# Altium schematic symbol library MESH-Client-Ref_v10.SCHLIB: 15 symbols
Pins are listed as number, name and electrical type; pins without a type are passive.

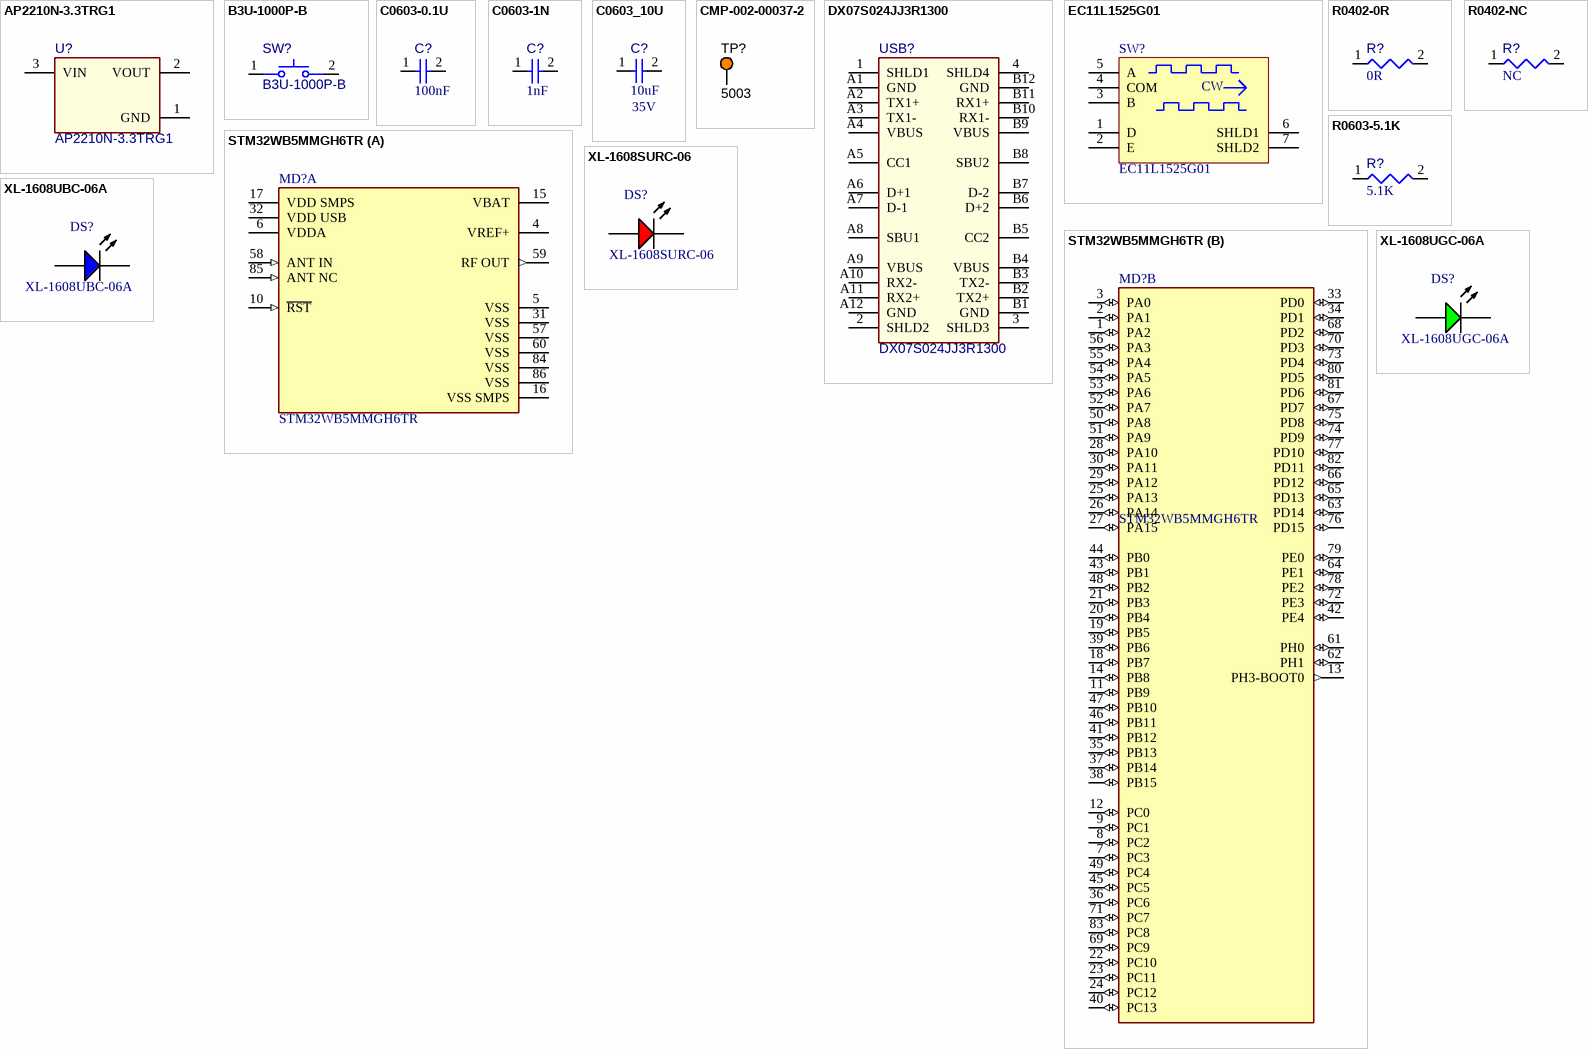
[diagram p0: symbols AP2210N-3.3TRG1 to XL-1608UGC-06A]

## AP2210N-3.3TRG1
designator U?
IC REG LINEAR 3.3V 300MA SOT23-3; Manufacturer: Diodes Incorporated
footprint SOT23-3 (SOT23, 3-Leads, Body 2.96x2.83mm, Pitch 0.95mm, IPC Medium Density)
pins: 1 GND (power) "Common ground", 2 VOUT (power) "Output voltage. A 1-uF Low ESR capacitor should be connected to this pin. Connect this output to the load circuit. An internal 280 Ohm discharge resistor prevents a charge remaining on VOUT when VEN is low.", 3 VIN (power) "Input voltage supply. A 1-µF capacitor should be connected at this input."

## B3U-1000P-B
designator SW?
Ultra-small Surface-mounting Tactile Switches with High Contact Reliability, SPST-NO, -25 to 70 degC, 2-Pin SMD, RoHS, Tape and Reel; Manufacturer: Omron; Voltage Rating: 12V
footprint OMRON-B3U-1000P-2-B_V (SMT, 2-Leads, Body 3x2.5mm)
pins: 1, 2

## C0603-0.1U
designator C?, comment value 100nF  (hidden comment: 0.1uF)
CAP CER 0.1UF 16V X7R 0603; Manufacturer: Murata Electronics; Part Number: GCJ188R71C104KA01D
footprint C0603 (Chip Capacitor, 2-Leads, Body 1.60x0.80mm, IPC Medium Density)
pins: 1, 2

## C0603-1N
designator C?, comment 1nF
CAP CER 1000PF 50V C0G/NP0 0603; Manufacturer: Murata Electronics; Part Number: GRM1885C1H102JA01D
footprint C0603 (Chip Capacitor, 2-Leads, Body 1.60x0.80mm, IPC Medium Density)
pins: 1, 2

## C0603_10U
designator C?, comment Voltage Rating: 35V  (hidden comment: 10uF)
CAP CER 10UF 35V X5R 0603; Part Number: GRM188R6YA106MA73D; Manufacturer: Murata
footprint C0603 (Chip Capacitor, 2-Leads, Body 1.60x0.80mm, IPC Medium Density)
pins: 1, 2

## CMP-002-00037-2
designator TP?, comment 5003  (no BOM)
Test Point, Orange, Height 4.6 mm, Tail Length 3 mm, 1-Pin THD, RoHS; Manufacturer: Keystone; Manufacturer 1: Keystone Electronics
footprint KSTN-5003 (Test Point, Through Hole, Dia 2.54mm)
pins: 1

## DX07S024JJ3R1300
designator USB?
USB-C Connector, 20 V, 1.25 A, -30 to 80 degC, RoHS, Tape and Reel; Manufacturer: JAE Electronics; Gender: Receptacle
footprint JAE-DX07S024JJ3_V (THD, 24-Leads, Body 8.17x8.94mm, Pitch 0.5mm)
pins: 1 SHLD1, 2 SHLD2, 3 SHLD3, 4 SHLD4, A1 GND, A2 TX1+, A3 TX1-, A4 VBUS, A5 CC1, A6 D+1, A7 D-1, A8 SBU1, A9 VBUS, A10 RX2-, A11 RX2+, A12 GND, B1 GND, B2 TX2+, B3 TX2-, B4 VBUS, B5 CC2, B6 D+2, B7 D-2, B8 SBU2, B9 VBUS, B10 RX1-, B11 RX1+, B12 GND

## EC11L1525G01
designator SW?
Plugin Rotary Encoders ROHS; Manufacturer: ALPSALPINE
footprint EC11L1525G01
pins: 1 D, 2 E, 3 B "Channel B", 4 COM "Common", 5 A "Channel A", 6 SHLD1, 7 SHLD2

## R0402-0R
designator R?, comment 0R
RES 0 OHM JUMPER 1/16W 0402; Manufacturer: Yageo; Part Number: RC0402FR-070RL
footprint R0402 (Chip Resistor, 2-Leads, Body 1.00x0.50mm, IPC Medium Density)
pins: 1, 2
1 alternate drawing of the same symbol

## R0402-NC
designator R?, comment NC  (no BOM)
RES NC 0402
footprint R0402 (Chip Resistor, 2-Leads, Body 1.00x0.50mm, IPC Medium Density)
pins: 1, 2
1 alternate drawing of the same symbol

## R0603-5.1K
designator R?, comment 5.1K
RES 5.1K OHM 1% 1/10W 0603; Manufacturer: Yageo; Part Number: RC0603FR-075K1L
footprint R0603 (Chip Resistor, 2-Leads, Body 1.65x0.85mm, IPC Medium Density)
pins: 1, 2
1 alternate drawing of the same symbol

## STM32WB5MMGH6TR
designator MD?
ULTRA-LOW-POWER DUAL CORE ARM CO; Manufacturer: STMicroelectronics; Part Number: PX32WB5MMGH6TR
footprint FP-STM32WB5MMGH6TR-MFG
part A pins: 4 VREF+ (power), 5 VSS (power), 6 VDDA (power), 10 ~{RST} (in), 15 VBAT (power), 16 VSS SMPS (power), 17 VDD SMPS (power), 31 VSS (power), 32 VDD USB (power), 57 VSS (power), 58 ANT IN (in), 59 RF OUT (out), 60 VSS (power), 84 VSS (power), 85 ANT NC (in), 86 VSS (power)
part B pins: 1 PA2 (io), 2 PA1 (io), 3 PA0 (io), 7 PC3 (io), 8 PC2 (io), 9 PC1 (io), 11 PB9 (io), 12 PC0 (io), 13 PH3-BOOT0 (out), 14 PB8 (io), 18 PB7 (io), 19 PB5 (io), 20 PB4 (io), 21 PB3 (io), 22 PC10 (io), 23 PC11 (io), 24 PC12 (io), 25 PA13 (io), 26 PA14 (io), 27 PA15 (io), 28 PA10 (io), 29 PA12 (io), 30 PA11 (io), 33 PD0 (io), 34 PD1 (io), 35 PB13 (io), 36 PC6 (io), 37 PB14 (io), 38 PB15 (io), 39 PB6 (io), 40 PC13 (io), 41 PB12 (io), 42 PE4 (io), 43 PB1 (io), 44 PB0 (io), 45 PC5 (io), 46 PB11 (io), 47 PB10 (io), 48 PB2 (io), 49 PC4 (io), 50 PA8 (io), 51 PA9 (io), 52 PA7 (io), 53 PA6 (io), 54 PA5 (io), 55 PA4 (io), 56 PA3 (io), 61 PH0 (io), 62 PH1 (io), 63 PD14 (io), 64 PE1 (io), 65 PD13 (io), 66 PD12 (io), 67 PD7 (io), 68 PD2 (io), 69 PC9 (io), 70 PD3 (io), 71 PC7 (io), 72 PE3 (io), 73 PD4 (io), 74 PD9 (io), 75 PD8 (io), 76 PD15 (io), 77 PD10 (io), 78 PE2 (io), 79 PE0 (io), 80 PD5 (io), 81 PD6 (io), 82 PD11 (io), 83 PC8 (io)

## XL-1608SURC-06
designator DS?
CHIP LED 0603 RED SMD; Manufacturer: XINGLIGHT
footprint LED0603 (Chip Diode, 2-Leads, Body 1.65x0.85mm, IPC Medium Density)
pins: 1 A, 2 K

## XL-1608UBC-06A
designator DS?
CHIP LED 0603 BLUE SMD; Manufacturer: XINGLIGHT
footprint LED0603 (Chip Diode, 2-Leads, Body 1.65x0.85mm, IPC Medium Density)
pins: 1 A, 2 K

## XL-1608UGC-06A
designator DS?
CHIP LED 0603 GREEN SMD; Manufacturer: XINGLIGHT
footprint LED0603 (Chip Diode, 2-Leads, Body 1.65x0.85mm, IPC Medium Density)
pins: 1 A, 2 K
